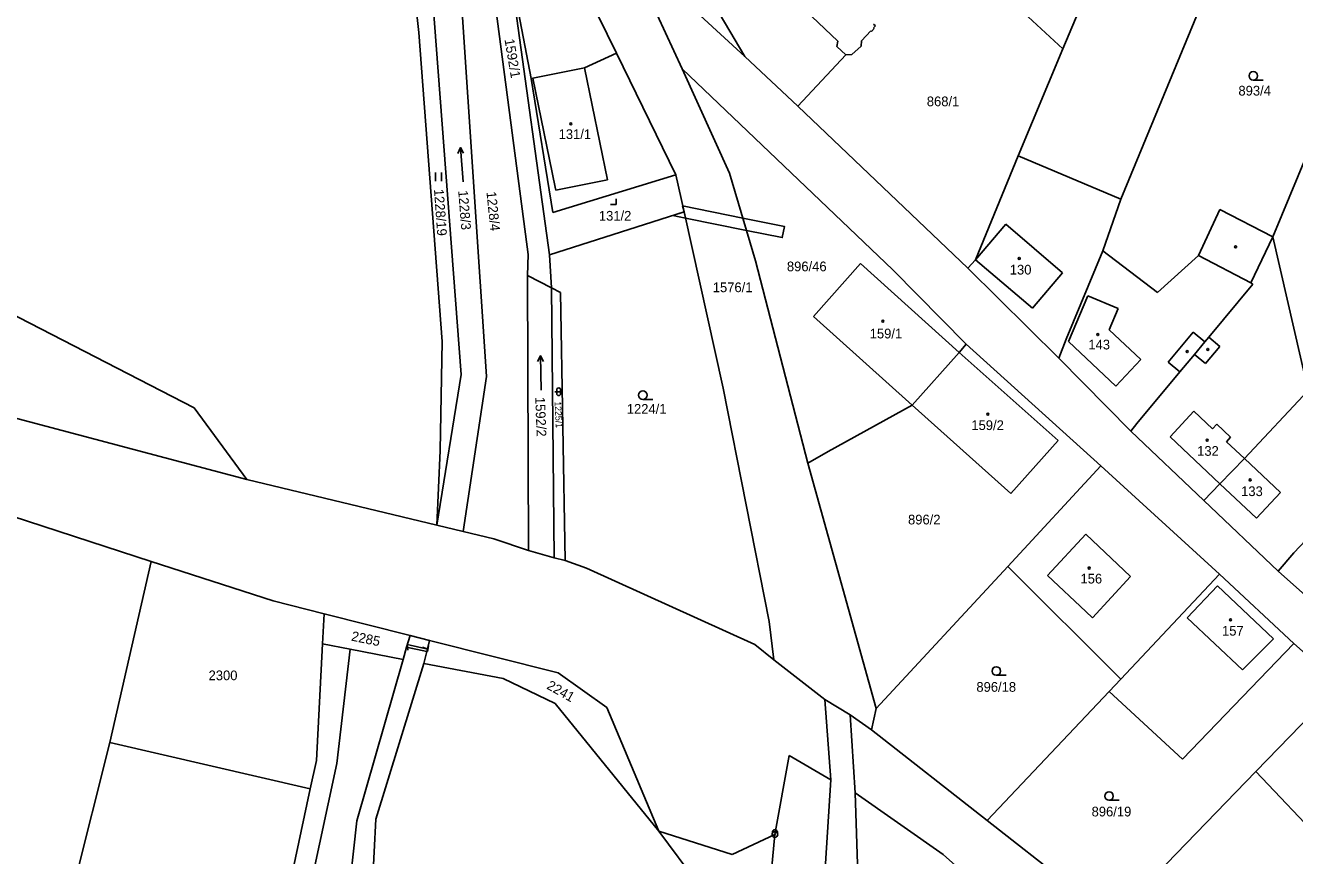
# Model space of a CAD drawing. Extents: x -801826 to -800592, y -1032871 to -1031813.
# Drawn here: x -801124.4 to -800902.2, y -1032698.5 to -1032553.2 of the extents above; entities that cross this region are included whole.
import ezdxf

# ---------------------------------------------------------------- set-up
doc = ezdxf.new("R2010")
doc.units = 0
for name, color, linetype in [('Vrstva 1', 7, 'Continuous'), ('Vrstva 18', 7, 'Continuous'), ('Vrstva 19', 7, 'Continuous'), ('Vrstva 24', 7, 'Continuous'), ('Vrstva 25', 7, 'Continuous'), ('Vrstva 26', 7, 'Continuous'), ('Vrstva 27', 7, 'Continuous'), ('Vrstva 4', 7, 'Continuous')]:
    doc.layers.add(name, color=color, linetype=linetype)

msp = doc.modelspace()

# ---------------------------------------------------------------- linework, layer by layer
at = {"layer": 'Vrstva 1'}
for p, q in [((-800932.59, -1032583.57), (-800908.24, -1032524.68)), ((-801009.42, -1032560.77), (-801019.25, -1032539.53)), ((-801020.95, -1032558.06), (-801029.77, -1032540.01)), ((-800961.62, -1032539.82), (-800942.75, -1032557.29)), ((-800906.01, -1032590.17), (-800885.17, -1032539.97)), ((-801035.88, -1032562.46), (-801039.61, -1032543.05)), ((-801039.61, -1032543.05), (-801032.64, -1032593.34)), ((-801055.52, -1032554.44), (-801056.37, -1032546.95)), ((-801048.16, -1032614.25), (-801053.17, -1032547.78)), ((-800998.43, -1032558.61), (-801010.64, -1032547.43)), ((-800998.43, -1032558.61), (-801004.92, -1032547.69)), ((-801043.7, -1032614.64), (-801048.06, -1032549.12)), ((-801036.42, -1032593.26), (-801042.02, -1032550.66)), ((-800939.42, -1032549.38), (-800942.75, -1032557.29)), ((-800975.93, -1032552.97), (-800975.6, -1032553.27)), ((-801051.47, -1032608.53), (-801055.52, -1032554.44)), ((-800976.4, -1032554.14), (-800978, -1032555.89)), ((-800976.29, -1032554.24), (-800976.4, -1032554.14)), ((-800975.79, -1032553.69), (-800976.29, -1032554.24)), ((-800975.6, -1032553.27), (-800975.9, -1032553.59)), ((-800975.9, -1032553.59), (-800975.79, -1032553.69)), ((-800978.11, -1032556.79), (-800979.74, -1032558.27)), ((-800978, -1032555.89), (-800978.11, -1032556.79)), ((-800942.75, -1032557.29), (-800950.62, -1032576.01)), ((-801026.53, -1032560.58), (-801020.95, -1032558.06)), ((-801010.57, -1032579.3), (-801020.95, -1032558.06)), ((-800989.17, -1032567.32), (-800998.43, -1032558.61)), ((-800980.79, -1032558.35), (-800989.17, -1032567.32)), ((-800979.74, -1032558.27), (-800980.79, -1032558.35)), ((-801035.58, -1032562.4), (-801026.53, -1032560.58)), ((-801009.42, -1032560.77), (-800972.52, -1032595.98)), ((-801001.17, -1032579.06), (-801009.42, -1032560.77)), ((-801035.58, -1032562.4), (-801035.88, -1032562.46)), ((-801035.88, -1032562.46), (-801032.11, -1032585.91)), ((-800959.43, -1032595.68), (-800989.17, -1032567.32)), ((-801188.33, -1032572.02), (-801094.89, -1032620.09)), ((-801094.89, -1032620.09), (-801188.33, -1032572.02)), ((-800950.62, -1032576.01), (-800958.06, -1032594.19)), ((-800950.62, -1032576.01), (-800932.59, -1032583.57)), ((-801032.11, -1032585.91), (-801010.57, -1032579.3)), ((-801009.11, -1032585.83), (-801010.57, -1032579.3)), ((-800996.58, -1032594.41), (-801001.17, -1032579.06)), ((-800932.59, -1032583.57), (-800935.76, -1032592.65)), ((-801032.64, -1032593.34), (-801009.11, -1032585.83)), ((-801002.23, -1032616.67), (-801009.11, -1032585.83)), ((-800915.25, -1032585.4), (-800919, -1032593.44)), ((-800906.01, -1032590.17), (-800915.25, -1032585.4)), ((-800909.87, -1032598.24), (-800906.01, -1032590.17)), ((-800899.82, -1032617.08), (-800906.01, -1032590.17)), ((-801271.57, -1032592.07), (-801102.43, -1032646.99)), ((-800942.18, -1032608.12), (-800935.76, -1032592.65)), ((-800935.76, -1032592.65), (-800926.21, -1032599.92)), ((-801036.53, -1032596.94), (-801036.42, -1032593.26)), ((-801032.64, -1032593.34), (-801032.29, -1032599.13)), ((-800987.43, -1032629.78), (-800996.58, -1032594.41)), ((-800986.44, -1032604.15), (-800978.19, -1032594.87)), ((-800960.91, -1032610.42), (-800978.19, -1032594.87)), ((-800958.06, -1032594.19), (-800959.43, -1032595.68)), ((-800926.21, -1032599.92), (-800919, -1032593.44)), ((-801085.65, -1032632.67), (-801218.53, -1032597.39)), ((-801218.53, -1032597.39), (-801085.65, -1032632.67)), ((-801036.53, -1032596.94), (-801032.29, -1032599.13)), ((-801036.35, -1032645.09), (-801036.53, -1032596.94)), ((-800972.52, -1032595.98), (-800959.71, -1032608.99)), ((-800943.47, -1032611.4), (-800959.43, -1032595.68)), ((-801032.29, -1032599.13), (-801031.82, -1032646.37)), ((-801032.29, -1032599.13), (-801030.73, -1032599.93)), ((-800917.22, -1032607.76), (-800909.47, -1032598.45)), ((-800909.47, -1032598.45), (-800909.87, -1032598.24)), ((-801030.73, -1032599.93), (-801029.92, -1032646.86)), ((-800969.15, -1032619.62), (-800986.44, -1032604.15)), ((-801051.83, -1032627.59), (-801051.47, -1032608.53)), ((-800943.47, -1032611.4), (-800942.18, -1032608.12)), ((-800919.71, -1032610.76), (-800917.91, -1032608.58)), ((-800917.91, -1032608.58), (-800917.22, -1032607.76)), ((-800969.15, -1032619.62), (-800960.91, -1032610.42)), ((-800959.71, -1032608.99), (-800960.91, -1032610.42)), ((-800943.56, -1032625.85), (-800960.91, -1032610.42)), ((-800936.09, -1032630.27), (-800959.71, -1032608.99)), ((-800922.26, -1032613.81), (-800919.71, -1032610.76)), ((-800930.89, -1032624.21), (-800943.47, -1032611.4)), ((-801052.4, -1032640.65), (-801048.16, -1032614.25)), ((-801047.79, -1032641.76), (-801043.7, -1032614.64)), ((-800929.79, -1032622.86), (-800922.26, -1032613.81)), ((-800994.22, -1032657.49), (-801002.23, -1032616.67)), ((-800899.82, -1032617.08), (-800910.98, -1032628.99)), ((-800969.15, -1032619.62), (-800983.85, -1032627.78)), ((-800951.86, -1032635.09), (-800969.15, -1032619.62)), ((-801094.89, -1032620.09), (-801085.65, -1032632.67)), ((-801085.65, -1032632.67), (-801094.89, -1032620.09)), ((-800930.89, -1032624.21), (-800929.79, -1032622.86)), ((-800943.56, -1032625.85), (-800951.86, -1032635.09)), ((-800918.09, -1032636.33), (-800930.89, -1032624.21)), ((-801051.83, -1032627.59), (-801052.4, -1032640.65)), ((-800983.85, -1032627.78), (-800987.43, -1032629.78)), ((-800987.43, -1032629.78), (-800975.47, -1032672.72)), ((-800952.41, -1032647.86), (-800936.09, -1032630.27)), ((-800915.36, -1032649.24), (-800936.09, -1032630.27)), ((-800915.27, -1032633.41), (-800910.98, -1032628.99)), ((-800902.29, -1032645.52), (-800888.19, -1032630.36)), ((-801052.4, -1032640.65), (-801085.65, -1032632.67)), ((-800918.09, -1032636.33), (-800915.27, -1032633.41)), ((-800905.05, -1032648.69), (-800918.09, -1032636.33)), ((-801047.79, -1032641.76), (-801052.4, -1032640.65)), ((-801042.41, -1032643.05), (-801047.79, -1032641.76)), ((-801042.41, -1032643.05), (-801036.35, -1032645.09)), ((-801031.82, -1032646.37), (-801036.35, -1032645.09)), ((-801029.92, -1032646.86), (-801031.82, -1032646.37)), ((-800905.05, -1032648.69), (-800902.29, -1032645.52)), ((-801109.69, -1032678.67), (-801102.43, -1032646.99)), ((-801102.43, -1032646.99), (-801081.07, -1032653.92)), ((-801026.19, -1032648.2), (-801029.92, -1032646.86)), ((-800996.71, -1032661.53), (-801026.19, -1032648.2)), ((-800975.47, -1032672.72), (-800952.41, -1032647.86)), ((-800952.41, -1032647.86), (-800932.64, -1032667.62)), ((-800932.64, -1032667.62), (-800915.36, -1032649.24)), ((-800902.29, -1032661.37), (-800915.36, -1032649.24)), ((-800891.41, -1032660.9), (-800905.05, -1032648.69)), ((-801081.07, -1032653.92), (-801072.12, -1032656.18)), ((-801072.4, -1032661.45), (-801072.12, -1032656.18)), ((-801072.12, -1032656.18), (-801057.08, -1032659.97)), ((-800993.37, -1032664.2), (-800994.22, -1032657.49)), ((-801073.49, -1032681.87), (-801072.4, -1032661.45)), ((-801067.58, -1032662.37), (-801072.4, -1032661.45)), ((-801057.68, -1032662), (-801057.08, -1032659.97)), ((-801057.08, -1032659.97), (-801053.66, -1032660.83)), ((-801053.66, -1032660.83), (-801054.15, -1032662.75)), ((-801053.66, -1032660.83), (-801031.12, -1032666.51)), ((-800993.37, -1032664.2), (-800996.71, -1032661.53)), ((-800921.79, -1032681.6), (-800902.29, -1032661.37)), ((-800894.26, -1032668.56), (-800902.29, -1032661.37)), ((-801069.91, -1032682.34), (-801067.58, -1032662.37)), ((-801067.58, -1032662.37), (-801058.31, -1032664.15)), ((-801066.39, -1032692.38), (-801058.31, -1032664.15)), ((-801058.31, -1032664.15), (-801057.68, -1032662)), ((-801054.15, -1032662.75), (-801054.68, -1032664.84)), ((-801054.68, -1032664.84), (-801063.09, -1032692.11)), ((-801054.68, -1032664.84), (-801040.76, -1032667.51)), ((-800984.47, -1032671.17), (-800993.37, -1032664.2)), ((-801040.76, -1032667.51), (-801031.67, -1032671.85)), ((-801031.12, -1032666.51), (-801022.63, -1032672.56)), ((-800934.63, -1032669.74), (-800932.64, -1032667.62)), ((-800908.97, -1032683.75), (-800894.26, -1032668.56)), ((-800956, -1032692.32), (-800934.63, -1032669.74)), ((-800934.63, -1032669.74), (-800921.79, -1032681.6)), ((-801031.67, -1032671.85), (-801013.5, -1032694.24)), ((-801022.63, -1032672.56), (-801013.5, -1032694.24)), ((-800980.02, -1032673.86), (-800984.47, -1032671.17)), ((-800984.47, -1032671.17), (-800983.39, -1032685.2)), ((-800976.27, -1032676.45), (-800975.47, -1032672.72)), ((-800979.16, -1032687.51), (-800980.02, -1032673.86)), ((-800980.02, -1032673.86), (-800976.27, -1032676.45)), ((-800956, -1032692.32), (-800976.27, -1032676.45)), ((-801139.8, -1032799.16), (-801109.69, -1032678.67)), ((-801109.69, -1032678.67), (-801074.55, -1032686.82)), ((-801073.49, -1032681.87), (-801074.55, -1032686.82)), ((-800993.19, -1032694.8), (-800990.72, -1032680.96)), ((-800990.72, -1032680.96), (-800983.39, -1032685.2)), ((-801080.45, -1032731.35), (-801069.91, -1032682.34)), ((-800933.97, -1032709.57), (-800908.97, -1032683.75)), ((-800908.97, -1032683.75), (-800896.63, -1032696.82)), ((-800983.39, -1032685.2), (-800986.84, -1032739.57)), ((-801074.55, -1032686.82), (-801083.96, -1032730.55)), ((-800963.73, -1032698.31), (-800979.16, -1032687.51)), ((-800979.16, -1032687.51), (-800978.56, -1032704.27)), ((-801068.16, -1032707.98), (-801066.39, -1032692.38)), ((-801063.09, -1032692.11), (-801064.82, -1032725.47)), ((-800933.97, -1032709.57), (-800956, -1032692.32)), ((-801013.5, -1032694.24), (-801005.01, -1032705.58)), ((-801013.5, -1032694.24), (-801000.67, -1032698.31)), ((-801000.67, -1032698.31), (-800993.19, -1032694.8)), ((-800993.19, -1032694.8), (-800994.97, -1032713.82)), ((-800936.91, -1032722.01), (-800963.73, -1032698.31))]:
    msp.add_line(p, q, dxfattribs=at)
at = {"layer": 'Vrstva 24'}
for radius in [0.5, 0.0364]:
    msp.add_circle((-800993.19, -1032694.8), radius, dxfattribs=at)
msp.add_arc((-800993.19, -1032694.43), 0.45, 344.4473, 196.3778, dxfattribs=at)
at = {"layer": 'Vrstva 25'}
for p, q in [((-800907.66, -1032562.77), (-800909.41, -1032562.77)), ((-801047.81, -1032580.55), (-801048.27, -1032574.57)), ((-801052.63, -1032578.92), (-801052.63, -1032580.42)), ((-801051.6, -1032580.42), (-801051.6, -1032578.92)), ((-801021.01, -1032584.53), (-801021.01, -1032583.53)), ((-801022.01, -1032584.53), (-801021.01, -1032584.53)), ((-801034.13, -1032617), (-801034.27, -1032611)), ((-801031.73, -1032617.29), (-801030.39, -1032617.29)), ((-801031.4, -1032617.62), (-801031.4, -1032616.96)), ((-801030.72, -1032617.62), (-801030.72, -1032616.96)), ((-801014.57, -1032618.63), (-801016.32, -1032618.63)), ((-800952.67, -1032666.93), (-800954.42, -1032666.93)), ((-800932.93, -1032688.81), (-800934.68, -1032688.81))]:
    msp.add_line(p, q, dxfattribs=at)
for points in [[(-801048.69, -1032575.6), (-801048.27, -1032574.57), (-801047.7, -1032575.53)], [(-801034.74, -1032612.01), (-801034.27, -1032611), (-801033.74, -1032611.99)]]:
    msp.add_lwpolyline(points, dxfattribs=at)
for centre, radius in [((-800909.41, -1032562.02), 0.75), ((-801028.94, -1032570.38), 0.175), ((-800912.51, -1032591.94), 0.175), ((-800950.39, -1032593.97), 0.175), ((-800974.27, -1032604.96), 0.175), ((-800936.65, -1032607.28), 0.175), ((-800920.98, -1032610.27), 0.175), ((-800917.39, -1032609.89), 0.175), ((-801016.32, -1032617.88), 0.75), ((-800955.89, -1032621.22), 0.175), ((-800917.48, -1032625.78), 0.175), ((-800909.98, -1032632.74), 0.175), ((-800938.16, -1032648.15), 0.175), ((-800913.39, -1032657.24), 0.175), ((-800954.42, -1032666.18), 0.75), ((-800934.68, -1032688.06), 0.75)]:
    msp.add_circle(centre, radius, dxfattribs=at)
for centre, start, end in [((-801031.06, -1032616.96), 0, 180), ((-801031.06, -1032617.62), 180, 0)]:
    msp.add_arc(centre, 0.335, start, end, dxfattribs=at)
at = {"layer": 'Vrstva 26'}
for p, q in [((-801057.6, -1032661.54), (-801057.47, -1032662.53)), ((-801054.04, -1032662.77), (-801053.84, -1032661.79)), ((-801057.7, -1032662), (-801056.72, -1032662.21)), ((-801053.97, -1032662.37), (-801054.89, -1032661.98))]:
    msp.add_line(p, q, dxfattribs=at)
at = {"layer": 'Vrstva 27'}
for points in [[(-801008.87, -1032586.91), (-801011.07, -1032586.47), (-801011.07, -1032586.45), (-801009.11, -1032585.83), (-801008.87, -1032586.91)], [(-801009.35, -1032584.77), (-800998.83, -1032586.89), (-800998.18, -1032589.06), (-801008.87, -1032586.91), (-801009.11, -1032585.83), (-801009.35, -1032584.77)], [(-800998.83, -1032586.89), (-800991.52, -1032588.36), (-800991.91, -1032590.32), (-800998.18, -1032589.06), (-800998.83, -1032586.89)]]:
    msp.add_lwpolyline(points, dxfattribs=at)
at = {"layer": 'Vrstva 4'}
for p, q in [((-800989.02, -1032549.47), (-800982.17, -1032555.91)), ((-800982.32, -1032556.85), (-800982.17, -1032555.91)), ((-800980.79, -1032558.35), (-800982.32, -1032556.85)), ((-801026.53, -1032560.58), (-801022.5, -1032580.2)), ((-801031.69, -1032581.46), (-801035.58, -1032562.4)), ((-801031.69, -1032581.46), (-801031.57, -1032582.04)), ((-801031.57, -1032582.04), (-801022.5, -1032580.2)), ((-800958.06, -1032594.19), (-800952.75, -1032587.95)), ((-800952.75, -1032587.95), (-800942.83, -1032596.51)), ((-800948.09, -1032602.67), (-800958.06, -1032594.19)), ((-800919, -1032593.44), (-800909.87, -1032598.24)), ((-800942.83, -1032596.51), (-800948.09, -1032602.67)), ((-800941.78, -1032608.5), (-800938.4, -1032600.51)), ((-800933.1, -1032602.75), (-800938.4, -1032600.51)), ((-800934.66, -1032606.47), (-800933.1, -1032602.75)), ((-800941.78, -1032608.5), (-800933.46, -1032616.3)), ((-800929.12, -1032611.67), (-800934.66, -1032606.47)), ((-800924.3, -1032612.11), (-800919.95, -1032606.89)), ((-800919.95, -1032606.89), (-800917.91, -1032608.58)), ((-800915.3, -1032609.36), (-800917.22, -1032607.76)), ((-800919.71, -1032610.76), (-800917.79, -1032612.35)), ((-800917.79, -1032612.35), (-800915.3, -1032609.36)), ((-800933.46, -1032616.3), (-800929.12, -1032611.67)), ((-800922.26, -1032613.81), (-800924.3, -1032612.11)), ((-800919.81, -1032620.72), (-800924, -1032625.19)), ((-800916.55, -1032623.77), (-800919.81, -1032620.72)), ((-800915.79, -1032622.97), (-800916.55, -1032623.77)), ((-800913.38, -1032625.23), (-800915.79, -1032622.97)), ((-800915.27, -1032633.41), (-800924, -1032625.19)), ((-800914.13, -1032626.04), (-800913.38, -1032625.23)), ((-800910.98, -1032628.99), (-800914.13, -1032626.04)), ((-800910.98, -1032628.99), (-800904.64, -1032634.93)), ((-800908.83, -1032639.4), (-800915.27, -1032633.41)), ((-800904.64, -1032634.93), (-800908.83, -1032639.4)), ((-800945.43, -1032649.45), (-800938.74, -1032642.24)), ((-800938.74, -1032642.24), (-800930.9, -1032649.61)), ((-800945.43, -1032649.45), (-800938.75, -1032655.77)), ((-800937.57, -1032656.86), (-800930.9, -1032649.61)), ((-800920.97, -1032656.87), (-800915.7, -1032651.28)), ((-800915.7, -1032651.28), (-800905.9, -1032660.52)), ((-800938.75, -1032655.77), (-800937.57, -1032656.86)), ((-800911.32, -1032665.97), (-800920.97, -1032656.87)), ((-801057.7, -1032662), (-801057.6, -1032661.54)), ((-801057.6, -1032661.54), (-801053.97, -1032662.37)), ((-800905.9, -1032660.52), (-800911.32, -1032665.97)), ((-801057.7, -1032662), (-801057.68, -1032662)), ((-801057.68, -1032662), (-801054.15, -1032662.75)), ((-801054.15, -1032662.75), (-801054.04, -1032662.77)), ((-801053.97, -1032662.37), (-801054.04, -1032662.77))]:
    msp.add_line(p, q, dxfattribs=at)

# ---------------------------------------------------------------- texts
at = {"layer": 'Vrstva 18'}
for s, height, rotation, p in [('1592/1', 1.7, 279.5742, (-801040.55, -1032555.65)), ('1228/19', 1.7, 274.1297, (-801052.9, -1032581.87)), ('1228/3', 1.7, 274.6534, (-801048.66, -1032582.11)), ('1228/4', 1.7, 275.7824, (-801043.71, -1032582.33)), ('1592/2', 1.7, 272.1986, (-801035.17, -1032618.24)), ('1225/1', 1.14, 272.8804, (-801031.78, -1032619.01)), ('2285', 1.7, 348.3583, (-801067.47, -1032660.84)), ('2241', 1.7, 330.654, (-801033.3, -1032669.2))]:
    msp.add_text(s, height=height, rotation=rotation, dxfattribs=at).set_placement(p)
for s, p in [('893/4', (-800912.02, -1032565.45)), ('868/1', (-800966.59, -1032567.32)), ('896/46', (-800991.09, -1032596.21)), ('1576/1', (-801004.07, -1032599.87)), ('1224/1', (-801019.13, -1032621.15)), ('896/2', (-800969.88, -1032640.52)), ('2300', (-801092.37, -1032667.79)), ('896/18', (-800957.91, -1032669.81)), ('896/19', (-800937.73, -1032691.63))]:
    msp.add_text(s, height=1.7, dxfattribs=at).set_placement(p)
at = {"layer": 'Vrstva 19'}
for s, p in [('131/1', (-801031.07, -1032573.06)), ('131/2', (-801024.02, -1032587.35)), ('130', (-800952.06, -1032596.78)), ('159/1', (-800976.59, -1032607.96)), ('143', (-800938.3, -1032609.89)), ('159/2', (-800958.79, -1032624)), ('132', (-800919.25, -1032628.51)), ('133', (-800911.55, -1032635.56)), ('156', (-800939.68, -1032650.86)), ('157', (-800914.89, -1032659.98))]:
    msp.add_text(s, height=1.7, dxfattribs=at).set_placement(p)

doc.saveas('drawing.dxf')
